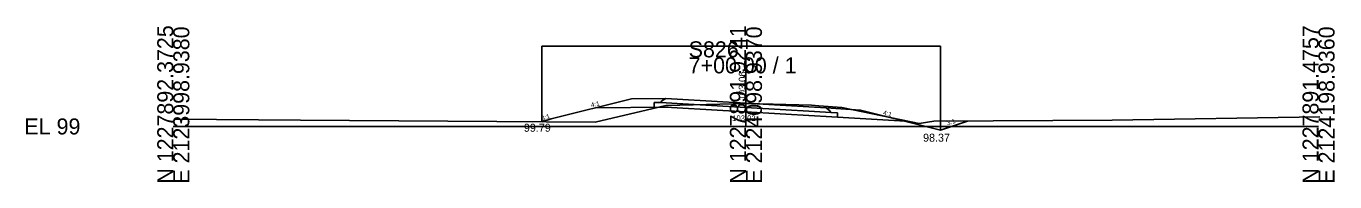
# Model space of a CAD drawing. Extents: x 2118382 to 2118616, y 1213030 to 1222057.
# Drawn here: x 2118381.9 to 2118610.4, y 1217530.1 to 1217557.3 of the extents above; entities that cross this region are included whole.
import ezdxf

# ---------------------------------------------------------------- set-up
doc = ezdxf.new("R2010")
doc.units = 0
for name, color, linetype in [('XS_CELL', 7, 'Continuous'), ('XS_M_DITCH', 7, 'Continuous'), ('XS_P_FINISHED_GRADE', 7, 'Continuous'), ('XS_P_FINISHED_GRADE_ELEV_TX', 7, 'Continuous'), ('XS_P_SUBGRADE_GRANULAR', 7, 'Continuous'), ('XS_P_SUBGRADE_PAVEMENT', 7, 'Continuous'), ('XS_P_TX_DCH', 7, 'Continuous'), ('XS_P_TX_FS_BS', 7, 'Continuous'), ('XS_X_GROUND', 7, 'Continuous'), ('XS_X_GROUND_TX', 7, 'Continuous')]:
    doc.layers.add(name, color=color, linetype=linetype)

msp = doc.modelspace()

# ---------------------------------------------------------------- linework, layer by layer
at = {"layer": 'XS_CELL'}
for p, q in [((2118507.6, 1217539.8), (2118507.6, 1217551.88)), ((2118407.6, 1217539.8), (2118507.6, 1217539.8)), ((2118507.6, 1217539.8), (2118607.6, 1217539.8))]:
    msp.add_line(p, q, dxfattribs=at)
at = {"layer": 'XS_M_DITCH'}
for p, q in [((2118471.98, 1217540.59), (2118471.98, 1217553.86)), ((2118471.98, 1217553.86), (2118541.6, 1217553.86)), ((2118541.6, 1217553.86), (2118541.6, 1217539.17))]:
    msp.add_line(p, q, dxfattribs=at)
at = {"layer": 'XS_P_FINISHED_GRADE'}
for p, q in [((2118487.6, 1217544.63), (2118473.6, 1217541.13)), ((2118493.6, 1217544.69), (2118487.6, 1217544.63)), ((2118495.6, 1217544.58), (2118493.6, 1217544.69)), ((2118495.6, 1217544.58), (2118507.6, 1217543.86)), ((2118507.6, 1217543.86), (2118519.6, 1217543.15)), ((2118519.6, 1217543.15), (2118521.6, 1217543.03)), ((2118521.6, 1217543.03), (2118527.6, 1217542.67)), ((2118527.6, 1217542.67), (2118541.6, 1217539.17)), ((2118473.6, 1217541.13), (2118471.98, 1217540.59)), ((2118541.6, 1217539.17), (2118546.3, 1217540.74))]:
    msp.add_line(p, q, dxfattribs=at)
at = {"layer": 'XS_P_SUBGRADE_GRANULAR'}
for p, q in [((2118492.73, 1217544), (2118491.6, 1217543.98)), ((2118493.6, 1217543.19), (2118481.34, 1217543.06)), ((2118491.6, 1217543.17), (2118491.6, 1217543.98)), ((2118495.6, 1217543.08), (2118493.6, 1217543.19)), ((2118495.6, 1217543.08), (2118507.6, 1217542.36)), ((2118507.6, 1217542.36), (2118519.6, 1217541.65)), ((2118522.44, 1217542.23), (2118523.6, 1217542.16)), ((2118523.6, 1217541.41), (2118523.6, 1217542.16)), ((2118519.6, 1217541.65), (2118521.6, 1217541.53)), ((2118521.6, 1217541.53), (2118523.6, 1217541.41)), ((2118523.6, 1217541.41), (2118535.47, 1217540.71))]:
    msp.add_line(p, q, dxfattribs=at)
at = {"layer": 'XS_P_SUBGRADE_PAVEMENT'}
for p, q in [((2118492.89, 1217544.28), (2118492.73, 1217544)), ((2118495.6, 1217543.83), (2118492.73, 1217544)), ((2118493.6, 1217544.69), (2118492.89, 1217544.28)), ((2118495.6, 1217543.83), (2118507.6, 1217543.11)), ((2118507.6, 1217543.11), (2118519.6, 1217542.4)), ((2118519.6, 1217542.4), (2118522.44, 1217542.23)), ((2118521.6, 1217543.03), (2118522.26, 1217542.53)), ((2118522.26, 1217542.53), (2118522.44, 1217542.23))]:
    msp.add_line(p, q, dxfattribs=at)
at = {"layer": 'XS_X_GROUND'}
for p, q in [((2118481.28, 1217540.52), (2118492.41, 1217543.15)), ((2118492.41, 1217543.15), (2118493.64, 1217543.45)), ((2118493.64, 1217543.45), (2118494.03, 1217543.47)), ((2118494.03, 1217543.47), (2118496.08, 1217543.52)), ((2118496.08, 1217543.52), (2118505.4, 1217543.76)), ((2118505.4, 1217543.76), (2118507.6, 1217543.82)), ((2118507.6, 1217543.82), (2118512.38, 1217543.69)), ((2118512.38, 1217543.69), (2118519.05, 1217543.5)), ((2118519.05, 1217543.5), (2118520.32, 1217543.39)), ((2118520.32, 1217543.39), (2118524.35, 1217543.11)), ((2118524.35, 1217543.11), (2118529.68, 1217542.02)), ((2118529.68, 1217542.02), (2118537.85, 1217540.33)), ((2118407.81, 1217541.1), (2118429.82, 1217540.92)), ((2118429.82, 1217540.92), (2118481.28, 1217540.52)), ((2118537.85, 1217540.33), (2118540.43, 1217540.7)), ((2118540.43, 1217540.7), (2118571.56, 1217540.92)), ((2118571.56, 1217540.92), (2118607.81, 1217541.45))]:
    msp.add_line(p, q, dxfattribs=at)

# ---------------------------------------------------------------- texts
at = {"layer": 'XS_CELL'}
for s, p in [('N 1227892.3725', (2118407.6, 1217529.8)), ('E 2123998.9380', (2118410.4, 1217529.8)), ('N 1227891.9241', (2118507.6, 1217529.8)), ('E 2124098.9370', (2118510.4, 1217529.8)), ('N 1227891.4757', (2118607.6, 1217529.8)), ('E 2124198.9360', (2118610.4, 1217529.8))]:
    msp.add_text(s, height=2.8, rotation=90, dxfattribs=at).set_placement(p)
for s, p in [('S826', (2118497.6, 1217551.88)), ('7+00.00 / 1', (2118497.6, 1217549.08)), ('EL 99', (2118381.6, 1217538.4))]:
    msp.add_text(s, height=2.8, dxfattribs=at).set_placement(p)
at = {"layer": 'XS_P_FINISHED_GRADE_ELEV_TX'}
msp.add_text(' 103.06', height=1.25, rotation=90, dxfattribs=at).set_placement((2118507.6, 1217543.86))
at = {"layer": 'XS_P_TX_DCH'}
for s, p in [('99.79', (2118468.83, 1217538.87)), ('98.37', (2118538.54, 1217537.13))]:
    msp.add_text(s, height=1.4, dxfattribs=at).set_placement(p)
at = {"layer": 'XS_P_TX_FS_BS'}
for s, rotation, p in [('4:1', 14.0362, (2118480.64, 1217543.12)), ('3:1', 18.4349, (2118471.99, 1217540.79)), ('4:1', 345.9638, (2118531.48, 1217541.86)), ('3:1', 18.404, (2118542.81, 1217539.96))]:
    msp.add_text(s, height=0.8, rotation=rotation, dxfattribs=at).set_placement(p)
at = {"layer": 'XS_X_GROUND_TX'}
msp.add_text('103.02', height=1, dxfattribs=at).set_placement((2118505.21, 1217540.73))

doc.saveas('drawing.dxf')
